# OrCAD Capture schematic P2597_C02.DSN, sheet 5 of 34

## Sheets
5 29_3V3 SLP AND 1.8V Vregs: size Custom
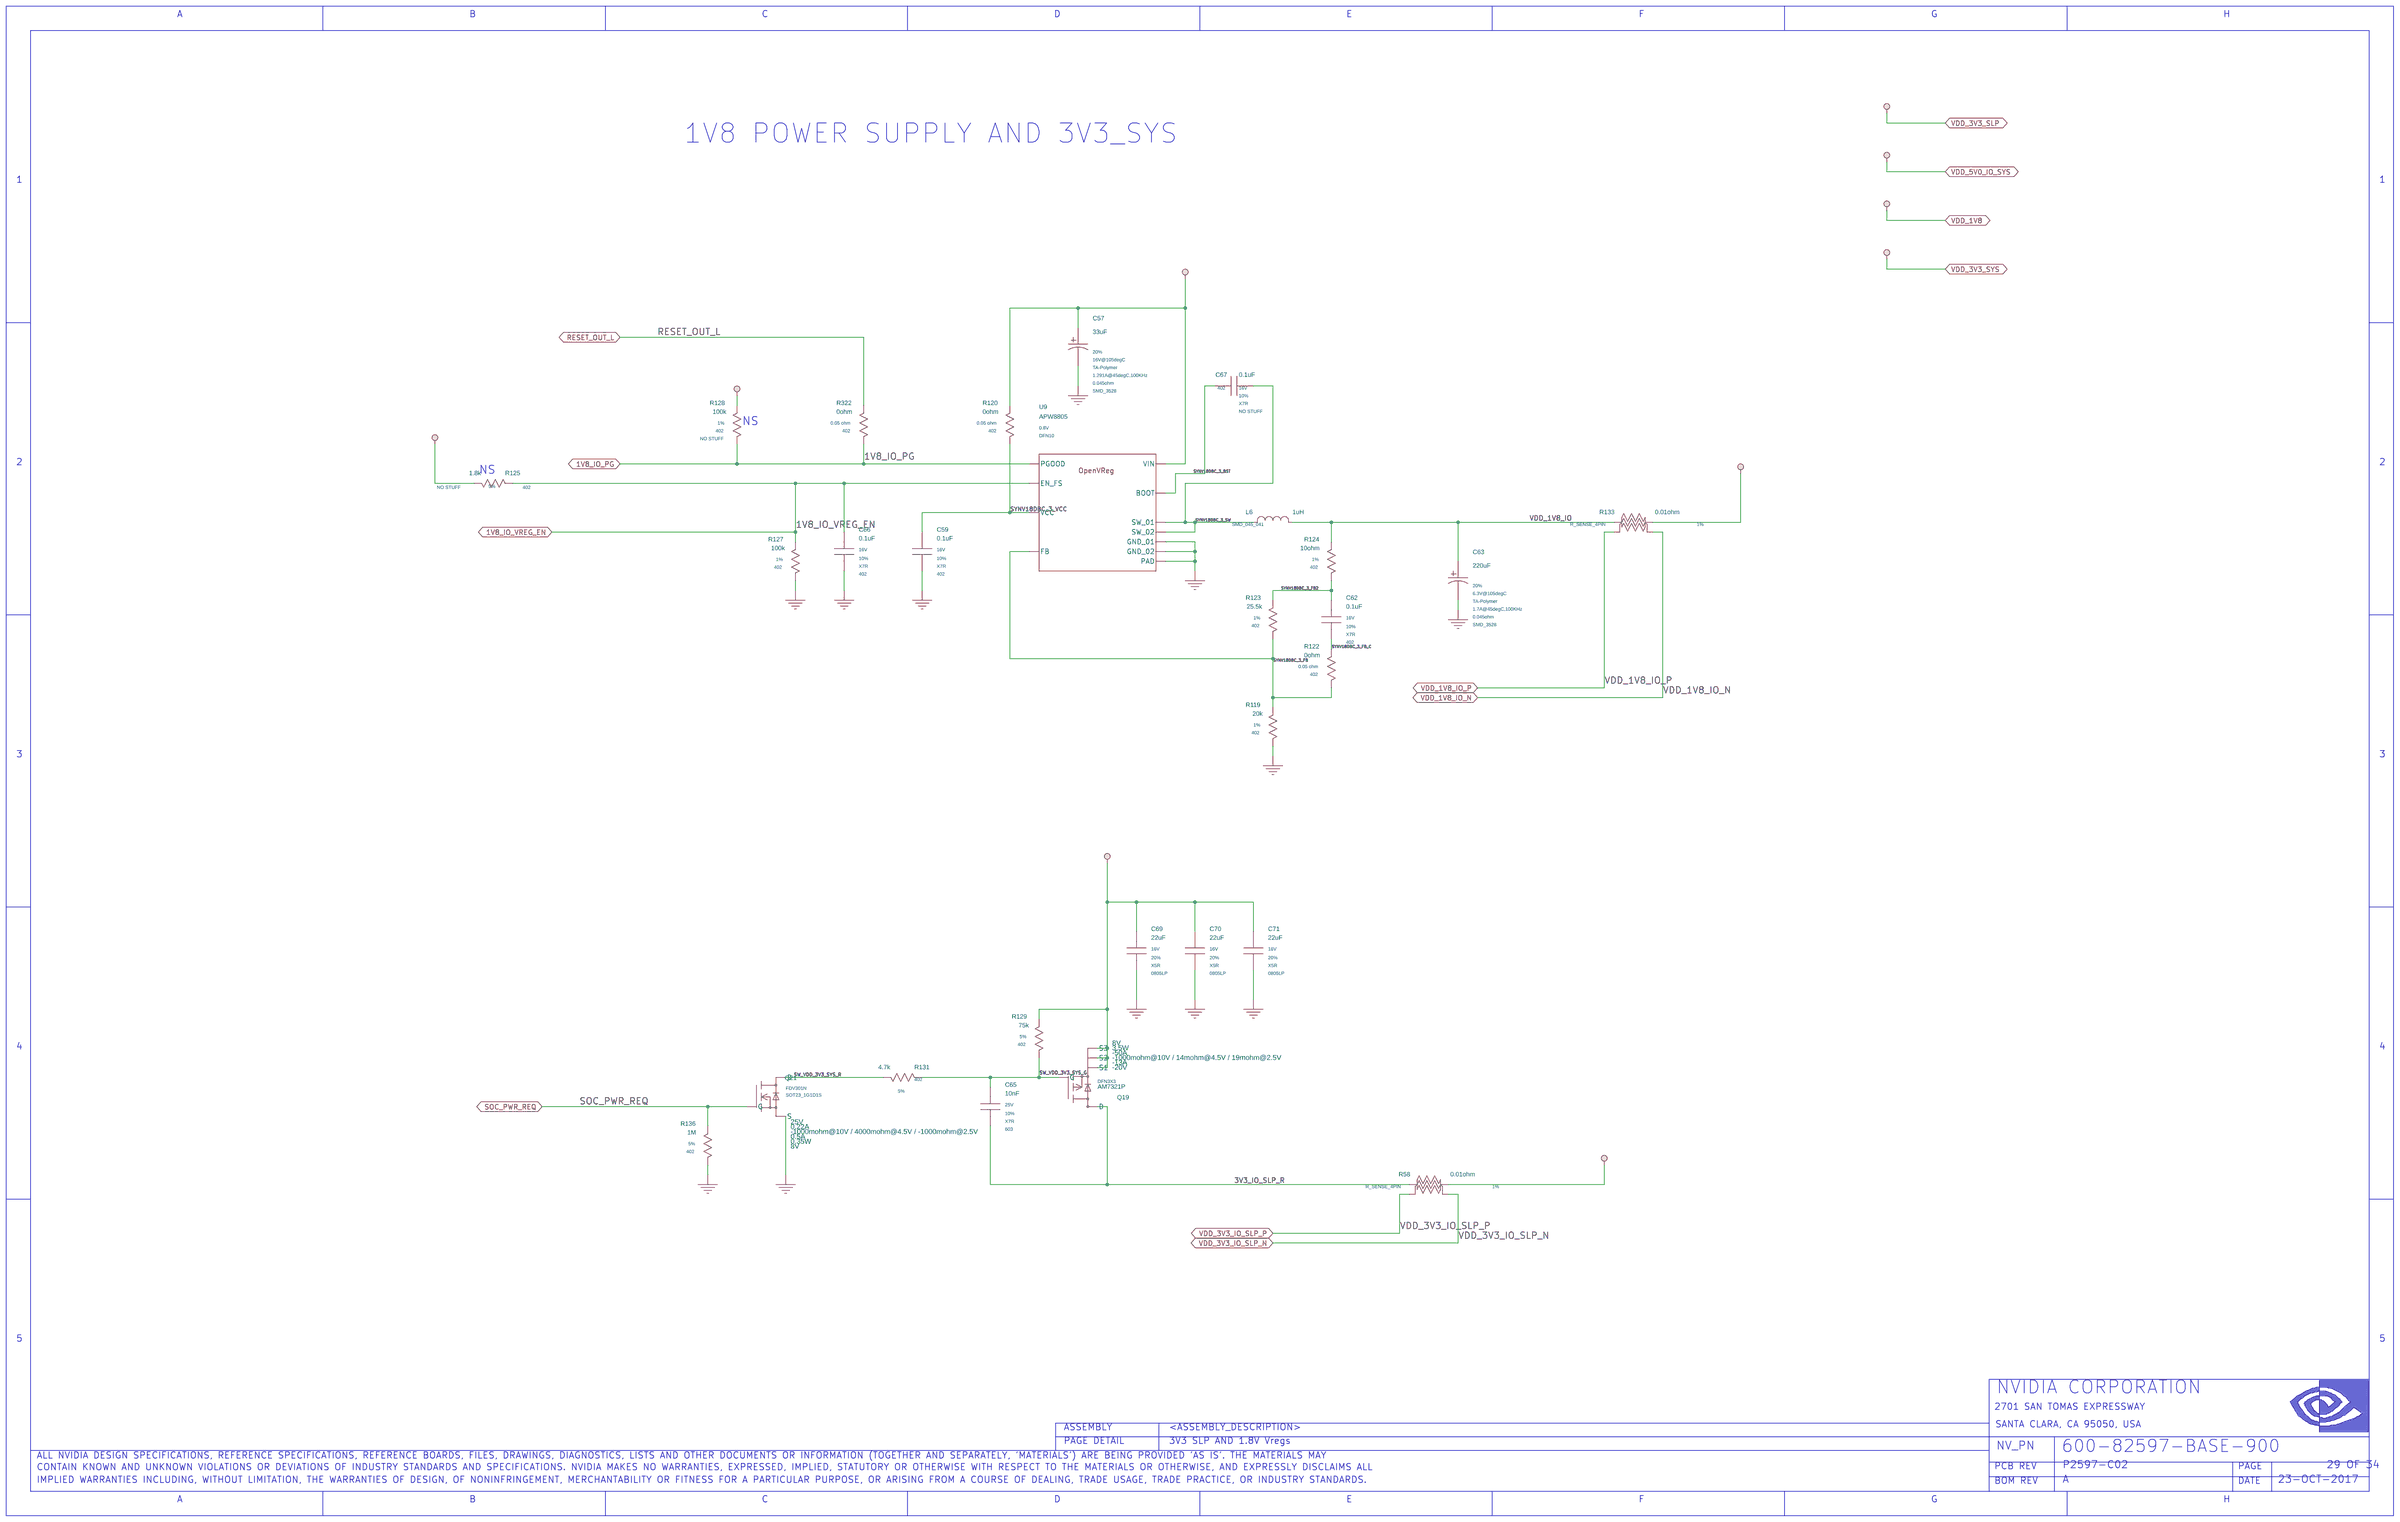
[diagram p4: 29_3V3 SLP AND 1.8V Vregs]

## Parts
C57  33uF  [CAP_SMD_3528]
C59  0.1uF  [402]
C62  0.1uF  [402]
C63  220uF  [CAP_SMD_3528]
C65  10nF  [603]
C66  0.1uF  [402]
C67  0.1uF  [402]
C69  22uF  [805]
C70  22uF  [805]
C71  22uF  [805]
L6  1uH  [IND_NONRKO_SMD_044X041]
Q19  Q_FET_P_ENH  [DFET_SMD_032X033]
Q21  Q_FET_N_ENH  [SOT23]
R58  0.01ohm  [RES_04_SMD_015X032]
R119  20k  [402]
R120  0ohm  [402]
R122  0ohm  [402]
R123  25.5k  [402]
R124  10ohm  [402]
R125  1.8k  [402]
R127  100k  [402]
R128  100k  [402]
R129  75k  [402]
R131  4.7k  [402]
R133  0.01ohm  [RES_04_SMD_015X032]
R136  1M  [402]
R322  0ohm  [402]
U9  0.8V  [DFN10_P050_030X030_T027X018_VIAS]

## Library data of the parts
C57 = C_POL: ASSEMBLY: VR_1V8_BACKUP; CDS_LIB: discrete; CDS_PART_NAME: C_POL_SMD_3528-33UF,TA-POLYMER,20%,16V@105DEGC,0.045OHM,9.999UH,1.291A@45DEGC,100KHZ,032-0468-000; CDS_PHYS_PART_NAME: C_POL_SMD_3528-33UF,TA-POLYMER,20%,16V@105DEGC,0.045OHM,9.999UH,1.291A@45DEGC,100KHZ,032-0468-000-032-0468-000,33UF; CDS_SEC: 1; DEVICE_TYPENAME: C_POL_SMD_3528-33UFTA-POLYMER2016V105DEGC0045OHM9999UH1291A45DEGC100KHZ032-0468-000-032-0468-00033UF; DRAWING: @P2597_C02_LIB.P2597_C02(SCH_1):PAGE29; ESL: 9.999uH; ESR: 0.045ohm; MAT: TA-Polymer; MAX_VOLTAGE: 16V@105degC; NV_PN: 032-0468-000; PACK_TYPE: SMD_3528; PATH: I401; PHYS_PAGE: 29; RIPPLE_CURRENT: 1.291A@45degC,100KHz; ROT: 0; SEC: 1; SIGNAL_MODEL: nv_capp; TOL: 20%; VER: 1; XY: -48,004,700
C59 = C: ASSEMBLY: VR_1V8_BACKUP; CDS_LIB: discrete; CDS_PART_NAME: C_0402-0.1UF,X7R,10%,16V,036-0014-000; CDS_PHYS_PART_NAME: C_0402-0.1UF,X7R,10%,16V,036-0014-000-0.1UF,036-0014-000; CDS_SEC: 1; DEVICE_TYPENAME: C_0402-01UFX7R1016V036-0014-000-01UF036-0014-000; DRAWING: @P2597_C02_LIB.P2597_C02(SCH_1):PAGE29; MAT: X7R; MAX_VOLTAGE: 16V; NV_PN: 036-0014-000; PATH: I365; PHYS_PAGE: 29; ROT: 0; SEC: 1; SIGNAL_MODEL: nv_cap; TOL: 10%; VER: 1; XY: -40,003,650
C62 = C: ASSEMBLY: VR_1V8_BACKUP; CDS_LIB: discrete; CDS_PART_NAME: C_0402-0.1UF,X7R,10%,16V,036-0014-000; CDS_PHYS_PART_NAME: C_0402-0.1UF,X7R,10%,16V,036-0014-000-0.1UF,036-0014-000; CDS_SEC: 1; DEVICE_TYPENAME: C_0402-01UFX7R1016V036-0014-000-01UF036-0014-000; DRAWING: @P2597_C02_LIB.P2597_C02(SCH_1):PAGE29; MAT: X7R; MAX_VOLTAGE: 16V; NV_PN: 036-0014-000; PATH: I238; PHYS_PAGE: 29; ROT: 0; SEC: 1; SIGNAL_MODEL: nv_cap; TOL: 10%; VER: 1; XY: -61,003,300
C63 = C_POL: ASSEMBLY: VR_1V8_BACKUP; CDS_LIB: discrete; CDS_PART_NAME: C_POL_SMD_3528-220UF,TA-POLYMER,20%,6.3V@105DEGC,0.045OHM,9.999UH,1.7A@45DEGC,100KHZ,041-0177-000; CDS_PHYS_PART_NAME: C_POL_SMD_3528-220UF,TA-POLYMER,20%,6.3V@105DEGC,0.045OHM,9.999UH,1.7A@45DEGC,100KHZ,041-0177-000-041-0177-000,220UF; CDS_SEC: 1; DEVICE_TYPENAME: C_POL_SMD_3528-220UFTA-POLYMER2063V105DEGC0045OHM9999UH17A45DEGC100KHZ041-0177-000-041-0177-000220UF; DRAWING: @P2597_C02_LIB.P2597_C02(SCH_1):PAGE29; ESL: 9.999uH; ESR: 0.045ohm; MAT: TA-Polymer; MAX_VOLTAGE: 6.3V@105degC; NV_PN: 041-0177-000; PACK_TYPE: SMD_3528; PATH: I406; PHYS_PAGE: 29; RIPPLE_CURRENT: 1.7A@45degC,100KHz; ROT: 0; SEC: 1; SIGNAL_MODEL: nv_capp; TOL: 20%; VER: 1; XY: -67,503,500
C65 = C: ASSEMBLY: SW_3V3; CDS_LIB: discrete; CDS_PART_NAME: C_0603-10NF,X7R,10%,25V,036-0042-000; CDS_PHYS_PART_NAME: C_0603-10NF,X7R,10%,25V,036-0042-000-036-0042-000,10NF; CDS_SEC: 1; DEVICE_TYPENAME: C_0603-10NFX7R1025V036-0042-000-036-0042-00010NF; DRAWING: @P2597_C02_LIB.P2597_C02(SCH_1):PAGE29; MAT: X7R; MAX_VOLTAGE: 25V; NV_PN: 036-0042-000; PATH: I380; PHYS_PAGE: 29; ROT: 0; SEC: 1; SIGNAL_MODEL: nv_cap; TOL: 10%; VER: 1; XY: -4,350,800
C66 = C: ASSEMBLY: VR_1V8_BACKUP; CDS_LIB: discrete; CDS_PART_NAME: C_0402-0.1UF,X7R,10%,16V,036-0014-000; CDS_PHYS_PART_NAME: C_0402-0.1UF,X7R,10%,16V,036-0014-000-0.1UF,036-0014-000; CDS_SEC: 1; DEVICE_TYPENAME: C_0402-01UFX7R1016V036-0014-000-01UF036-0014-000; DRAWING: @P2597_C02_LIB.P2597_C02(SCH_1):PAGE29; MAT: X7R; MAX_VOLTAGE: 16V; NV_PN: 036-0014-000; PATH: I374; PHYS_PAGE: 29; ROT: 0; SEC: 1; SIGNAL_MODEL: nv_cap; TOL: 10%; VER: 1; XY: -36,003,650
C67 = C#1: ASSEMBLY: VR_1V8_BACKUP; CDS_LIB: discrete; CDS_PART_NAME: C_0402-0.1UF,X7R,10%,16V,036-0014-000; CDS_PHYS_PART_NAME: C_0402-0.1UF,X7R,10%,16V,036-0014-000-0.1UF,036-0014-000; CDS_SEC: 1; CHIPS_PART_NAME: C; DEVICE_TYPENAME: C_0402-01UFX7R1016V036-0014-000-01UF036-0014-000; DRAWING: @P2597_C02_LIB.P2597_C02(SCH_1):PAGE29; MAT: X7R; MAX_VOLTAGE: 16V; NV_PN: 036-0014-000; PATH: I237; PHYS_PAGE: 29; ROT: 0; SEC: 1; SIGNAL_MODEL: nv_cap; SKU: NO STUFF; TOL: 10%; VER: 2; XY: -56,004,500
C69 = C: ASSEMBLY: SW_3V3; CDS_LIB: discrete; CDS_PART_NAME: C_0805LP-22UF,X5R,20%,16V,032-0195-000; CDS_PHYS_PART_NAME: C_0805LP-22UF,X5R,20%,16V,032-0195-000-032-0195-000,22UF; CDS_SEC: 1; DEVICE_TYPENAME: C_0805LP-22UFX5R2016V032-0195-000-032-0195-00022UF; DRAWING: @P2597_C02_LIB.P2597_C02(SCH_1):PAGE29; MAT: X5R; MAX_VOLTAGE: 16V; NV_PN: 032-0195-000; PACK_TYPE: 0805LP; PATH: I396; PHYS_PAGE: 29; ROT: 0; SEC: 1; SIGNAL_MODEL: nv_cap; TOL: 20%; VER: 1; XY: -51,001,600
C70 = C: ASSEMBLY: SW_3V3; CDS_LIB: discrete; CDS_PART_NAME: C_0805LP-22UF,X5R,20%,16V,032-0195-000; CDS_PHYS_PART_NAME: C_0805LP-22UF,X5R,20%,16V,032-0195-000-032-0195-000,22UF; CDS_SEC: 1; DEVICE_TYPENAME: C_0805LP-22UFX5R2016V032-0195-000-032-0195-00022UF; DRAWING: @P2597_C02_LIB.P2597_C02(SCH_1):PAGE29; MAT: X5R; MAX_VOLTAGE: 16V; NV_PN: 032-0195-000; PACK_TYPE: 0805LP; PATH: I394; PHYS_PAGE: 29; ROT: 0; SEC: 1; SIGNAL_MODEL: nv_cap; TOL: 20%; VER: 1; XY: -54,001,600
C71 = C: ASSEMBLY: SW_3V3; CDS_LIB: discrete; CDS_PART_NAME: C_0805LP-22UF,X5R,20%,16V,032-0195-000; CDS_PHYS_PART_NAME: C_0805LP-22UF,X5R,20%,16V,032-0195-000-032-0195-000,22UF; CDS_SEC: 1; DEVICE_TYPENAME: C_0805LP-22UFX5R2016V032-0195-000-032-0195-00022UF; DRAWING: @P2597_C02_LIB.P2597_C02(SCH_1):PAGE29; MAT: X5R; MAX_VOLTAGE: 16V; NV_PN: 032-0195-000; PACK_TYPE: 0805LP; PATH: I392; PHYS_PAGE: 29; ROT: 0; SEC: 1; SIGNAL_MODEL: nv_cap; TOL: 20%; VER: 1; XY: -57,001,600
L6 = L: ACOUSTIC_MARGIN: [ ]; ASSEMBLY: VR_1V8_BACKUP; CDS_LIB: discrete; CDS_PART_NAME: L_SMD_045_041-1UH,[ ],20%,5A,8.5A,0.027OHM,[ ]@[ ],[ ],[ ],131-0832-000; CDS_PHYS_PART_NAME: L_SMD_045_041-1UH,[ ],20%,5A,8.5A,0.027OHM,[ ]@[ ],[ ],[ ],131-0832-000-131-0832-000,1UH; CDS_SEC: 1; CONTINUOUS_CURRENT: 5A; DC_RESISTANCE: 0.027ohm; DEVICE_TYPENAME: L_SMD_045_041-1UH205A85A0027OHM131-0832-000-131-0832-0001UH; DRAWING: @P2597_C02_LIB.P2597_C02(SCH_1):PAGE29; MAT: [ ]; MAX_CURRENT: 8.5A; NV_PN: 131-0832-000; PACK_TYPE: SMD_045_041; PATH: I358; PHYS_PAGE: 29; Q: [ ]@[ ]; ROT: 0; SEC: 1; SEC_TYPE: SMD_045_041; SELF_RESONANCE_FREQ: [ ]; SIGNAL_MODEL: nv_ind; TOL: 20%; VER: 1; XY: -58,003,800
Q19 = Q_FET_P_ENH#1: ASSEMBLY: SW_3V3; CDS_LIB: discrete; CDS_PART_NAME: Q_FET_P_ENH_DFN3X3-AM7321P,-20V,-1000MOHM@10V / 14MOHM@4.5V / 19MOHM@2.5V,-13A,-50A,8V,3.5W,[ ]@10V / [ ]@4.5V / [ ]@2.5V,300-A; CDS_PHYS_PART_NAME: Q_FET_P_ENH_DFN3X3-AM7321P,-20V,-1000MOHM@10V / 14MOHM@4.5V / 19MOHM@2.5V,-13A,-50A,8V,3.5W,[ ]@10V / [ ]@4.5V / [ ]@2.5V,300-B; CDS_SEC: 1; CONTINUOUS_CURRENT: -13A; DEVICE_TYPENAME: Q_FET_P_ENH_DFN3X3-AM7321P-20V-1000MOHM10V14MOHM45V19MOHM25V-13A-50A8V35W10V45V25V300-B; DRAWING: @P2597_C02_LIB.P2597_C02(SCH_1):PAGE29; MAX_CURRENT: -50A; MAX_VOLTAGE: -20V; MAX_WATTAGE: 3.5W; NV_NAME: AM7321P; NV_PN: 300-0726-000; PACK_TYPE: DFN3X3; PATH: I382; PHYS_PAGE: 29; Q_G: [ ]@10V / [ ]@4.5V / [ ]@2.5V; ROT: 6; R_DS_ON: -1000mohm@10V / 14mohm@4.5V / 19mohm@2.5V; SEC: 1; VER: 8; V_BE_GS: 8V; XY: -4,800,900
Q21 = Q_FET_N_ENH#2: ASSEMBLY: SW_3V3; CDS_LIB: discrete; CDS_PART_NAME: Q_FET_N_ENH_SOT23_1G1D1S-FDV301N,25V,-1000MOHM@10V / 4000MOHM@4.5V / -1000MOHM@2.5V,0.22A,0.5A,8V,0.35W,[ ]@10V / [ ]@4.5V / [A; CDS_PHYS_PART_NAME: Q_FET_N_ENH_SOT23_1G1D1S-FDV301N,25V,-1000MOHM@10V / 4000MOHM@4.5V / -1000MOHM@2.5V,0.22A,0.5A,8V,0.35W,[ ]@10V / [ ]@4.5V / [B; CDS_SEC: 1; CONTINUOUS_CURRENT: 0.22A; CaptureCellPackProp: Q_FET_N_ENH__sym_2##2; DEVICE_TYPENAME: Q_FET_N_ENH_SOT23_1G1D1S-FDV301N25V-1000MOHM10V4000MOHM45V-1000MOHM25V022A05A8V035W10V45VB; DRAWING: @P2597_C02_LIB.P2597_C02(SCH_1):PAGE29; MAX_CURRENT: 0.5A; MAX_VOLTAGE: 25V; MAX_WATTAGE: 0.35W; NV_NAME: FDV301N; NV_PN: 300-0494-000; PACK_TYPE: SOT23_1G1D1S; PATH: I398; PHYS_PAGE: 29; Q_G: [ ]@10V / [ ]@4.5V / [ ]@2.5V; ROT: 0; R_DS_ON: -1000mohm@10V / 4000mohm@4.5V / -1000mohm@2.5V; SEC: 1; VER: 2; V_BE_GS: 8V; XY: -3,200,850
R58 = R_SENSE_4PIN: ASSEMBLY: SW_3V3; CDS_LIB: discrete; CDS_PART_NAME: R_SENSE_4PIN_R_SENSE_4PIN-0.01OHM,1%,1W,[ ],215-0142-000; CDS_PHYS_PART_NAME: R_SENSE_4PIN_R_SENSE_4PIN-0.01OHM,1%,1W,[ ],215-0142-000-0.01OHM,215-0142-000; CDS_SEC: 1; DEVICE_TYPENAME: R_SENSE_4PIN_R_SENSE_4PIN-001OHM11W215-0142-000-001OHM215-0142-000; DRAWING: @P2597_C02_LIB.P2597_C02(SCH_1):PAGE29; MAX_WATTAGE: 1W; NV_PN: 215-0142-000; PATH: I385; PHYS_PAGE: 29; ROT: 0; SEC: 1; SIGNAL_MODEL: nv_res_sense_4p_noxnet; TEMP_COEF: [ ]; TOL: 1%; VER: 1; XY: -6,600,400
R119 = R#1: ASSEMBLY: VR_1V8_BACKUP; CDS_LIB: discrete; CDS_PART_NAME: R_0402-20K,1 %,62.5MW,195-0150-000; CDS_PHYS_PART_NAME: R_0402-20K,1 %,62.5MW,195-0150-000-195-0150-000,20K; CDS_SEC: 1; CHIPS_PART_NAME: R; DEVICE_TYPENAME: R_0402-20K1625MW195-0150-000-195-0150-00020K; DRAWING: @P2597_C02_LIB.P2597_C02(SCH_1):PAGE29; MAX_WATTAGE: 62.5mW; NV_PN: 195-0150-000; PATH: I240; PHYS_PAGE: 29; ROT: 2; SEC: 1; SIGNAL_MODEL: nv_res; TOL: 1%; VER: 2; XY: -58,002,750
R120 = R#1: ASSEMBLY: VR_1V8_BACKUP; CDS_LIB: discrete; CDS_PART_NAME: R_0402-0OHM,0.05 OHM,62.5MW,195-2655-000; CDS_PHYS_PART_NAME: R_0402-0OHM,0.05 OHM,62.5MW,195-2655-000-0OHM,195-2655-000; CDS_SEC: 1; CHIPS_PART_NAME: R; DEVICE_TYPENAME: R_0402-0OHM005OHM625MW195-2655-000-0OHM195-2655-000; DRAWING: @P2597_C02_LIB.P2597_C02(SCH_1):PAGE29; MAX_WATTAGE: 62.5mW; NV_PN: 195-2655-000; PATH: I364; PHYS_PAGE: 29; ROT: 2; SEC: 1; SIGNAL_MODEL: nv_res; TOL: 0.05 ohm; VER: 2; XY: -44,504,300
R122 = R#1: ASSEMBLY: VR_1V8_BACKUP; CDS_LIB: discrete; CDS_PART_NAME: R_0402-0OHM,0.05 OHM,62.5MW,195-2655-000; CDS_PHYS_PART_NAME: R_0402-0OHM,0.05 OHM,62.5MW,195-2655-000-0OHM,195-2655-000; CDS_SEC: 1; CHIPS_PART_NAME: R; DEVICE_TYPENAME: R_0402-0OHM005OHM625MW195-2655-000-0OHM195-2655-000; DRAWING: @P2597_C02_LIB.P2597_C02(SCH_1):PAGE29; MAX_WATTAGE: 62.5mW; NV_PN: 195-2655-000; PATH: I367; PHYS_PAGE: 29; ROT: 2; SEC: 1; SIGNAL_MODEL: nv_res; TOL: 0.05 ohm; VER: 2; XY: -61,003,050
R123 = R#1: ASSEMBLY: VR_1V8_BACKUP; CDS_LIB: discrete; CDS_PART_NAME: R_0402-25.5K,1 %,62.5MW,195-0200-000; CDS_PHYS_PART_NAME: R_0402-25.5K,1 %,62.5MW,195-0200-000-195-0200-000,25.5K; CDS_SEC: 1; CHIPS_PART_NAME: R; DEVICE_TYPENAME: R_0402-255K1625MW195-0200-000-195-0200-000255K; DRAWING: @P2597_C02_LIB.P2597_C02(SCH_1):PAGE29; MAX_WATTAGE: 62.5mW; NV_PN: 195-0200-000; PATH: I239; PHYS_PAGE: 29; ROT: 2; SEC: 1; SIGNAL_MODEL: nv_res; TOL: 1%; VER: 2; XY: -58,003,300
R124 = R#1: ASSEMBLY: VR_1V8_BACKUP; CDS_LIB: discrete; CDS_PART_NAME: R_0402-10OHM,1 %,62.5MW,195-0001-000; CDS_PHYS_PART_NAME: R_0402-10OHM,1 %,62.5MW,195-0001-000-10OHM,195-0001-000; CDS_SEC: 1; CHIPS_PART_NAME: R; DEVICE_TYPENAME: R_0402-10OHM1625MW195-0001-000-10OHM195-0001-000; DRAWING: @P2597_C02_LIB.P2597_C02(SCH_1):PAGE29; MAX_WATTAGE: 62.5mW; NV_PN: 195-0001-000; PATH: I373; PHYS_PAGE: 29; ROT: 2; SEC: 1; SIGNAL_MODEL: nv_res; TOL: 1%; VER: 2; XY: -61,003,600
R125 = R: ASSEMBLY: VR_1V8_BACKUP; CDS_LIB: discrete; CDS_PART_NAME: R_0402-1.8K,5 %,62.5MW,195-0528-000; CDS_PHYS_PART_NAME: R_0402-1.8K,5 %,62.5MW,195-0528-000-1.8K,195-0528-000; CDS_SEC: 1; DEVICE_TYPENAME: R_0402-18K5625MW195-0528-000-18K195-0528-000; DRAWING: @P2597_C02_LIB.P2597_C02(SCH_1):PAGE29; MAX_WATTAGE: 62.5mW; NV_PN: 195-0528-000; PATH: I333; PHYS_PAGE: 29; ROT: 2; SEC: 1; SIGNAL_MODEL: nv_res; SKU: NO STUFF; TOL: 5%; VER: 1; XY: -18,004,000
R127 = R#1: ASSEMBLY: VR_1V8_BACKUP; CDS_LIB: discrete; CDS_PART_NAME: R_0402-100K,1 %,62.5MW,195-0005-000; CDS_PHYS_PART_NAME: R_0402-100K,1 %,62.5MW,195-0005-000-100K,195-0005-000; CDS_SEC: 1; CHIPS_PART_NAME: R; DEVICE_TYPENAME: R_0402-100K1625MW195-0005-000-100K195-0005-000; DRAWING: @P2597_C02_LIB.P2597_C02(SCH_1):PAGE29; MAX_WATTAGE: 62.5mW; NV_PN: 195-0005-000; PATH: I360; PHYS_PAGE: 29; ROT: 2; SEC: 1; SIGNAL_MODEL: nv_res; TOL: 1%; VER: 2; XY: -33,503,600
R128 = R#1: ASSEMBLY: VR_1V8_BACKUP; CDS_LIB: discrete; CDS_PART_NAME: R_0402-100K,1 %,62.5MW,195-0005-000; CDS_PHYS_PART_NAME: R_0402-100K,1 %,62.5MW,195-0005-000-100K,195-0005-000; CDS_SEC: 1; CHIPS_PART_NAME: R; DEVICE_TYPENAME: R_0402-100K1625MW195-0005-000-100K195-0005-000; DRAWING: @P2597_C02_LIB.P2597_C02(SCH_1):PAGE29; MAX_WATTAGE: 62.5mW; NV_PN: 195-0005-000; PATH: I264; PHYS_PAGE: 29; ROT: 2; SEC: 1; SIGNAL_MODEL: nv_res; SKU: NO STUFF; TOL: 1%; VER: 2; XY: -30,504,300
R129 = R#1: ASSEMBLY: SW_3V3; CDS_LIB: discrete; CDS_PART_NAME: R_0402-75K,5 %,62.5MW,195-0634-000; CDS_PHYS_PART_NAME: R_0402-75K,5 %,62.5MW,195-0634-000-195-0634-000,75K; CDS_SEC: 1; CHIPS_PART_NAME: R; DEVICE_TYPENAME: R_0402-75K5625MW195-0634-000-195-0634-00075K; DRAWING: @P2597_C02_LIB.P2597_C02(SCH_1):PAGE29; MAX_WATTAGE: 62.5mW; NV_PN: 195-0634-000; PATH: I381; PHYS_PAGE: 29; ROT: 2; SEC: 1; SIGNAL_MODEL: nv_res; TOL: 5%; VER: 2; XY: -46,001,150
R131 = R: ASSEMBLY: SW_3V3; CDS_LIB: discrete; CDS_PART_NAME: R_0402-4.7K,5 %,62.5MW,195-0598-000; CDS_PHYS_PART_NAME: R_0402-4.7K,5 %,62.5MW,195-0598-000-195-0598-000,4.7K; CDS_SEC: 1; DEVICE_TYPENAME: R_0402-47K5625MW195-0598-000-195-0598-00047K; DRAWING: @P2597_C02_LIB.P2597_C02(SCH_1):PAGE29; MAX_WATTAGE: 62.5mW; NV_PN: 195-0598-000; PATH: I379; PHYS_PAGE: 29; ROT: 2; SEC: 1; SIGNAL_MODEL: nv_res; TOL: 5%; VER: 1; XY: -3,900,950
R133 = R_SENSE_4PIN: ASSEMBLY: VR_1V8_BACKUP; CDS_LIB: discrete; CDS_PART_NAME: R_SENSE_4PIN_R_SENSE_4PIN-0.01OHM,1%,1W,[ ],215-0142-000; CDS_PHYS_PART_NAME: R_SENSE_4PIN_R_SENSE_4PIN-0.01OHM,1%,1W,[ ],215-0142-000-0.01OHM,215-0142-000; CDS_SEC: 1; DEVICE_TYPENAME: R_SENSE_4PIN_R_SENSE_4PIN-001OHM11W215-0142-000-001OHM215-0142-000; DRAWING: @P2597_C02_LIB.P2597_C02(SCH_1):PAGE29; MAX_WATTAGE: 1W; NV_PN: 215-0142-000; PATH: I335; PHYS_PAGE: 29; ROT: 0; SEC: 1; SIGNAL_MODEL: nv_res_sense_4p_noxnet; TEMP_COEF: [ ]; TOL: 1%; VER: 1; XY: -76,503,800
R136 = R#1: ASSEMBLY: SW_3V3; CDS_LIB: discrete; CDS_PART_NAME: R_0402-1M,5 %,62.5MW,195-0488-000; CDS_PHYS_PART_NAME: R_0402-1M,5 %,62.5MW,195-0488-000-195-0488-000,1M; CDS_SEC: 1; CHIPS_PART_NAME: R; DEVICE_TYPENAME: R_0402-1M5625MW195-0488-000-195-0488-0001M; DRAWING: @P2597_C02_LIB.P2597_C02(SCH_1):PAGE29; MAX_WATTAGE: 62.5mW; NV_PN: 195-0488-000; PATH: I389; PHYS_PAGE: 29; ROT: 2; SEC: 1; SIGNAL_MODEL: nv_res; TOL: 5%; VER: 2; XY: -2,900,600
R322 = R#1: ASSEMBLY: VR_1V8_BACKUP; CDS_LIB: discrete; CDS_PART_NAME: R_0402-0OHM,0.05 OHM,62.5MW,195-2655-000; CDS_PHYS_PART_NAME: R_0402-0OHM,0.05 OHM,62.5MW,195-2655-000-0OHM,195-2655-000; CDS_SEC: 1; CHIPS_PART_NAME: R; DEVICE_TYPENAME: R_0402-0OHM005OHM625MW195-2655-000-0OHM195-2655-000; DRAWING: @P2597_C02_LIB.P2597_C02(SCH_1):PAGE29; MAX_WATTAGE: 62.5mW; NV_PN: 195-2655-000; PATH: I418; PHYS_PAGE: 29; ROT: 2; SEC: 1; SIGNAL_MODEL: nv_res; TOL: 0.05 ohm; VER: 2; XY: -37,004,300
U9 = U_OPENVREG_TYPE0: ASSEMBLY: VR_1V8_BACKUP; CDS_LIB: power_supply; CDS_PART_NAME: U_OPENVREG_TYPE0_DFN10-APW8805,BUCK,1PH,1MHZ,NONE,0.6V..6V,1%,0.8V,6V,3A,1.429W,315-0832-000; CDS_PHYS_PART_NAME: U_OPENVREG_TYPE0_DFN10-APW8805,BUCK,1PH,1MHZ,NONE,0.6V..6V,1%,0.8V,6V,3A,1.429W,315-0832-000-0.8V,315-0832-000; CDS_SEC: 1; DEVICE_TYPENAME: U_OPENVREG_TYPE0_DFN10-APW8805BUCK1PH1MHZNONE06V6V108V6V3A1429W315-0832-000-08V315-0832-000; DRAWING: @P2597_C02_LIB.P2597_C02(SCH_1):PAGE29; MAX_CURRENT: 3A; MAX_VOLTAGE: 6V; MAX_WATTAGE: 1.429W; MODE: Buck; NV_NAME: APW8805; NV_PN: 315-0832-000; OUTPUT_VOLTAGE: 0.6V..6V; PACK_TYPE: DFN10; PATH: I243; PHASES: 1Ph; PHYS_PAGE: 29; PROGRAMMABLE: None; ROT: 0; SEC: 1; SEC_TYPE: DFN10; SWITCHING_FREQ: 1MHz; TOL: 1%; VER: 1; XY: -49,003,850

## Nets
1V8_IO_PG: R128.2 R322.2 U9.9(PGOOD) ; also on sheet 1
1V8_IO_VREG_EN: C66.1 R125.1 R127.1 U9.10(EN_FS) ; also on sheet 6
3V3_IO_SLP_R: C65.2 Q19.5(D) R58.1
GND: C57.2 C59.2 C63.2 C66.2 C69.2 C70.2 C71.2 Q21.2(S) R119.2 R127.2 R136.2 U9.4(GND_01) U9.5(GND_02) U9.11(PAD) ; also on sheet 1 2 3 4 6 7 9 10 11 12 13 14 15 16 17 18 19 20 21 22 23 24 25 26 30
VDD_1V8: R128.1 R133.4 ; also on sheet 4 9 10 12 13 16 17 18 19 20 22 24 30
VDD_1V8_IO: C63.1 L6.2 R124.1 R133.1
VDD_1V8_IO_N: R133.3 ; also on sheet 2
VDD_1V8_IO_P: R133.2 ; also on sheet 2
VDD_3V3_IO_SLP_N: R58.3 ; also on sheet 2
VDD_3V3_IO_SLP_P: R58.2 ; also on sheet 2
VDD_3V3_SLP: R58.4 ; also on sheet 4 11 16 17 20 21 22 25
VDD_3V3_SYS: C69.1 C70.1 C71.1 Q19.1(S1) Q19.2(S2) Q19.3(S3) R129.1 ; also on sheet 1 2 3 4 6 12 13 17 18 19 23 24 25
VDD_5V0_IO_SYS: C57.1 R120.1 R125.2 U9.3(VIN) ; also on sheet 4 6 9 11 12 16 17 18 20 22 26 30
RESET_OUT_L: R322.1 ; also on sheet 9 12 18 30
SOC_PWR_REQ: Q21.1(G) R136.1 ; also on sheet 12 15 30
SW_VDD_3V3_SYS_G: C65.1 Q19.4(G) R129.2 R131.1
SW_VDD_3V3_SYS_R: Q21.3(D) R131.2
SYNV18DBC_3_BST: C67.1 U9.8(BOOT)
SYNV18DBC_3_FB: R119.1 R122.2 R123.2 U9.1(FB)
SYNV18DBC_3_FB2: C62.1 R123.1 R124.2
SYNV18DBC_3_FB_C: C62.2 R122.1
SYNV18DBC_3_SW: C67.2 L6.1 U9.6(SW_01) U9.7(SW_02)
SYNV18DBC_3_VCC: C59.1 R120.2 U9.2(VCC)

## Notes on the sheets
sheet 5
- A
- B
- C
- D
- E
- F
- G
- H
- 1V8 POWER SUPPLY AND 3V3_SYS
- 1
- 1
- NS
- 2
- 2
- NS
- 3
- 3
- 4
- 4
- 5
- 5
- NVIDIA CORPORATION
- 2701 SAN TOMAS EXPRESSWAY
- ASSEMBLY
- <ASSEMBLY_DESCRIPTION>
- SANTA CLARA, CA 95050, USA
- PAGE DETAIL
- 3V3 SLP AND 1.8V Vregs
- NV_PN
- 600-82597-BASE-900
- ALL NVIDIA DESIGN SPECIFICATIONS, REFERENCE SPECIFICATIONS, REFERENCE BOARDS, FILES, DRAWINGS, DIAGNOSTICS, LISTS AND OTHER DOCUMENTS OR INFORMATION (TOGETHER AND SEPARATELY, 'MATERIALS') ARE BEING PROVIDED 'AS IS'. THE MATERIALS MAY
- CONTAIN KNOWN AND UNKNOWN VIOLATIONS OR DEVIATIONS OF INDUSTRY STANDARDS AND SPECIFICATIONS. NVIDIA MAKES NO WARRANTIES, EXPRESSED, IMPLIED, STATUTORY OR OTHERWISE WITH RESPECT TO THE MATERIALS OR OTHERWISE, AND EXPRESSLY DISCLAIMS ALL
- PCB REV
- P2597-C02
- PAGE
- 29 OF 34
- IMPLIED WARRANTIES INCLUDING, WITHOUT LIMITATION, THE WARRANTIES OF DESIGN, OF NONINFRINGEMENT, MERCHANTABILITY OR FITNESS FOR A PARTICULAR PURPOSE, OR ARISING FROM A COURSE OF DEALING, TRADE USAGE, TRADE PRACTICE, OR INDUSTRY STANDARDS.
- BOM REV
- A
- DATE
- 23-OCT-2017
- A
- B
- C
- D
- E
- F
- G
- H
